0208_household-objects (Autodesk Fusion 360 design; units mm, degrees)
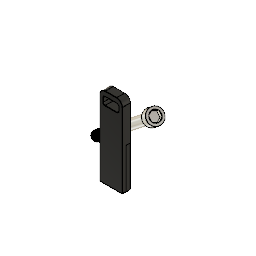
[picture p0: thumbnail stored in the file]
sketch "Screw 2D" plane through (0, 0, 0) normal (0, 1, 0) x axis (1, 0, 0)
  line L1 (0, 43) -> (0, 0)
  line L2 (4, 43) -> (0, 43)
  line L3 (4, 38.5) -> (4, 43)
  line L4 (2.5, 38.5) -> (4, 38.5)
  line L5 (2.5, 0) -> (2.5, 38.5)
  line L6 (2.5, 0) -> (0, 0)
  line L7 (2.5, 0) -> (0, 0)
  point P1 (0, 0)
  point P2 (0, 0)
  point P3 (0, 43)
  point P4 (4, 43)
  point P5 (4, 38.5)
  point P6 (2.5, 38.5)
  point P7 (2.5, 0)
  coincident P1 P2
  vertical L1
  perpendicular L1 L2
  perpendicular L2 L3
  perpendicular L3 L4
  perpendicular L4 L5
  dimension "d3" distance P2 P3 = 43
  dimension "d4" distance P3 P4 = 4
  dimension "d5" distance P4 P5 = 4.5
  dimension "d6" distance P5 P6 = 1.5
  dimension "d7" distance P6 P7 = 38.5
revolve "Revolve1" sketch "Screw 2D" AlongAngle 360
extrude "Extrude1" new body of existing geometry blind 21.5
thread "Thread1"
sketch "Sketch3" plane through (0, 0, -43) normal (0, 0, -1) x axis (1, 0, 0)
  line L1 (-1.3633, 2.3462) -> (1.3502, 2.3538)
  line L2 (-2.7135, -0.0076) -> (-1.3633, 2.3462)
  line L3 (-1.3502, -2.3538) -> (-2.7135, -0.0076)
  line L4 (1.3633, -2.3462) -> (-1.3502, -2.3538)
  line L5 (2.7135, 0.0076) -> (1.3633, -2.3462)
  line L6 (1.3502, 2.3538) -> (2.7135, 0.0076)
  circle C1 centre (0, 0) radius 4
  point P2 (0, 0)
  point P9 (0, 0)
  coincident P2 P9
  dimension "d12" distance P9 L6 = 2.35 (= "( 4.7 / 2 ) * 1 mm")
extrude "Extrude2" cut sketch "Sketch3" profile of L1 L2 L3 L4 L5 L6 against normal blind 2.5
sketch "Sketch4" plane through (0, 0, -43) normal (0, 0, -1) x axis (1, 0, 0)
  line L1 (1.3502, 2.3538) -> (-1.3633, 2.3462)
  line L2 (2.7135, 0.0076) -> (1.3502, 2.3538)
  line L3 (1.3633, -2.3462) -> (2.7135, 0.0076)
  line L4 (-1.3502, -2.3538) -> (1.3633, -2.3462)
  line L5 (-2.7135, -0.0076) -> (-1.3502, -2.3538)
  line L6 (-1.3633, 2.3462) -> (-2.7135, -0.0076)
  circle C1 centre (0, 0) radius 4
  circle C2 centre (0, 0) radius 2.7135
  point P5 (1.3633, -2.3462)
  concentric C1 C2
  coincident P5 C2
extrude "Extrude3" cut sketch "Sketch4" profile of C2 against normal blind 0.1 taper -45
chamfer "Chamfer1" distance 0.15
move "Move1"
move "Move2"
combine "Combine1"
component_from_bodies "Body->Comp"
sketch "Sketch1" plane through (0, 0, 0) normal (0, 1, 0) x axis (1, 0, 0)
  line L1 (12, 0) -> (0, 0)
  line L2 (12, -39.5) -> (12, 0)
  line L3 (3, -42.5) -> (9, -42.5)
  line L4 (0, 0) -> (0, -39.5)
  line L5 (1.9, -36.8611) -> (1.9, -38.9611)
  line L6 (9.1, -39.9611) -> (2.9, -39.9611)
  line L7 (10.1, -36.8611) -> (10.1, -38.9611)
  line L8 (2.9, -35.8611) -> (9.1, -35.8611)
  arc A1 centre (9, -39.5) radius 3 clockwise from (12, -39.5) to (9, -42.5)
  arc A2 centre (3, -39.5) radius 3 clockwise from (3, -42.5) to (0, -39.5)
  arc A3 centre (2.9, -38.9611) radius 1 clockwise from (2.9, -39.9611) to (1.9, -38.9611)
  arc A4 centre (2.9, -36.8611) radius 1 clockwise from (1.9, -36.8611) to (2.9, -35.8611)
  arc A5 centre (9.1, -36.8611) radius 1 clockwise from (9.1, -35.8611) to (10.1, -36.8611)
  arc A6 centre (9.1, -38.9611) radius 1 clockwise from (10.1, -38.9611) to (9.1, -39.9611)
  point P1 (0, 0)
  point P2 (0, 0)
  point P5 (0, 0)
  point P4 (12, -42.5)
  point P3 (12, 0)
  coincident P1 P2
  horizontal L1
  perpendicular L1 L2
  perpendicular L2 L3
  coincident P1 P5
  perpendicular L1 L4
  coincident P4 L2
  coincident P4 L3
  tangent L2 A1
  tangent L3 A1
  tangent L3 A2
  tangent L4 A2
  equal A1 A2
  vertical L5
  horizontal L6
  vertical L7
  horizontal L8
  tangent L5 A3
  tangent L6 A3
  tangent L5 A4
  tangent L8 A4
  equal A3 A4
  tangent L8 A5
  tangent L7 A5
  equal A3 A5
  tangent L6 A6
  tangent L7 A6
  equal A3 A6
  dimension "d18" distance P2 P3 = 12
  dimension "d19" distance P3 P4 = 42.5
  dimension "d20" radius A1 = 3
  dimension "d25" radius A3 = 1
sketch "Sketch2" plane through (6, 0, 21.25) normal (0, 1, 0) x axis (1, 0, 0)
extrude "Extrude1" new body sketch "Sketch1" along normal blind 4.4
fillet "Fillet1" radius 0.1
sketch "Sketch3" plane through (0, 0, 0) normal (0, 0, -1) x axis (1, 0, 0)
  line L1 (11.9, -4.4) -> (0.1, -4.4)
  line L2 (12, -0.1) -> (12, -4.3)
  line L3 (0.1, 0) -> (11.9, 0)
  line L4 (0, -4.3) -> (0, -0.1)
  line L5 (0.2, -4.2) -> (0.2, -0.2)
  line L6 (11.8, -4.2) -> (0.2, -4.2)
  line L7 (11.8, -0.2) -> (11.8, -4.2)
  line L8 (0.2, -0.2) -> (11.8, -0.2)
  arc A1 centre (0.1, -4.3) radius 0.1 clockwise from (0.1, -4.4) to (0, -4.3)
  arc A2 centre (11.9, -4.3) radius 0.1 clockwise from (12, -4.3) to (11.9, -4.4)
  arc A3 centre (11.9, -0.1) radius 0.1 clockwise from (11.9, 0) to (12, -0.1)
  arc A4 centre (0.1, -0.1) radius 0.1 clockwise from (0, -0.1) to (0.1, 0)
  dimension "d30" = -0.2
extrude "Extrude2" cut sketch "Sketch3" profile of L8 L6 L7 L5 against normal blind 21.2
sketch "Sketch4" plane through (0, 0, 21.2) normal (0, 0, -1) x axis (1, 0, 0)
  line L1 (0.2, -0.2) -> (11.8, -0.2)
  line L2 (0.2, -4.2) -> (0.2, -0.2)
  line L3 (11.8, -4.2) -> (0.2, -4.2)
  line L4 (11.8, -0.2) -> (11.8, -4.2)
  line L5 (11.8, -0.2) -> (0.2, -0.2)
  line L6 (11.8, -2.1) -> (11.8, -0.2)
  line L7 (0.2, -2.1) -> (11.8, -2.1)
  line L8 (0.2, -0.2) -> (0.2, -2.1)
  point P3 (0.2, -0.2)
  point P6 (0.2, -0.2)
  point P7 (11.8, -0.2)
  point P9 (0.2, -2.1)
  horizontal L5
  vertical L6
  horizontal L7
  vertical L8
  coincident P3 P6
  dimension "d33" distance P6 P7 = 11.6
  dimension "d34" distance P6 P9 = 1.9
extrude "Extrude3" add sketch "Sketch4" profile of L1 L2 L4 L5 L6 L7 L8 along normal blind 21.1
sketch "Sketch5" plane through (0, 0, 0.1) normal (0, 0, -1) x axis (1, 0, 0)
  line L1 (11.8, -2.1) -> (0.2, -2.1)
  line L2 (11.8, -0.2) -> (11.8, -2.1)
  line L3 (0.2, -0.2) -> (11.8, -0.2)
  line L4 (0.2, -2.1) -> (0.2, -0.2)
  line L5 (11.8, -0.8634) -> (0.2, -0.8634)
  line L6 (11.8, -1.3634) -> (11.8, -0.8634)
  line L7 (0.2, -1.3634) -> (11.8, -1.3634)
  line L8 (0.2, -0.8634) -> (0.2, -1.3634)
  point P6 (0.2, -0.8634)
  point P9 (0.2, -1.3634)
  horizontal L5
  vertical L6
  horizontal L7
  vertical L8
  coincident L4 P6
  dimension "d37" distance P6 P9 = 0.5
extrude "Extrude4" cut sketch "Sketch5" profile of L2 L4 L5 L6 L7 L8 against normal blind 0.2
move "Move1"
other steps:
base_feature "Base Feature"
create_component "CreateComponent1"
remove_body "RemoveBody1"
create_component "CreateComponent2"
